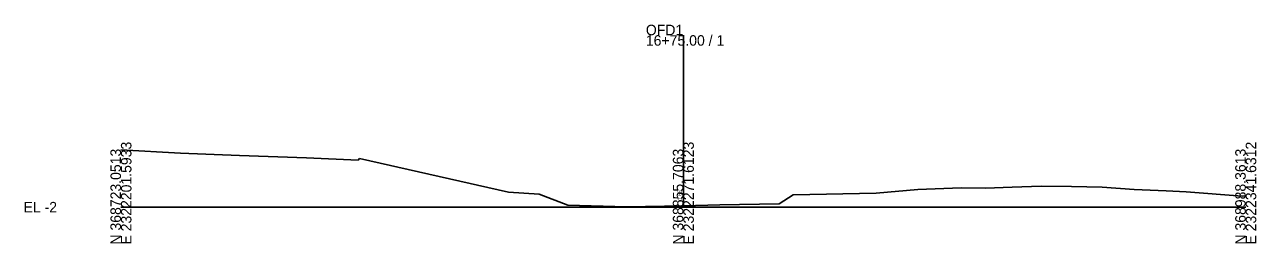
# Model space of a CAD drawing. Extents: x -26 to 303, y -10 to 14048.
# Drawn here: x -25.7 to 302.8, y 13490.3 to 13548.8 of the extents above; entities that cross this region are included whole.
import ezdxf

# ---------------------------------------------------------------- set-up
doc = ezdxf.new("R2010")
doc.units = 0
for name, color, linetype in [('RD_GPK_XS_Cell', 7, 'Continuous'), ('RD_XS_ExGround', 7, 'Continuous'), ('RD_XS_TX_Elev_EX', 7, 'Continuous')]:
    doc.layers.add(name, color=color, linetype=linetype)

msp = doc.modelspace()

# ---------------------------------------------------------------- linework, layer by layer
at = {"layer": 'RD_GPK_XS_Cell'}
for p, q in [((150, 13500), (150, 13545.96)), ((0, 13500), (150, 13500)), ((150, 13500), (300, 13500))]:
    msp.add_line(p, q, dxfattribs=at)
at = {"layer": 'RD_XS_ExGround'}
for p, q in [((0, 13515.32), (15.85, 13514.39)), ((15.85, 13514.39), (31.61, 13513.81)), ((31.61, 13513.81), (49.53, 13513.17)), ((49.53, 13513.17), (63.29, 13512.58)), ((63.29, 13512.58), (63.63, 13512.98)), ((63.63, 13512.98), (103.4, 13503.97)), ((103.4, 13503.97), (111.51, 13503.5)), ((111.51, 13503.5), (119.16, 13500.54)), ((175.53, 13500.93), (179.31, 13503.31)), ((179.31, 13503.31), (201.45, 13503.72)), ((201.45, 13503.72), (212.58, 13504.73)), ((212.58, 13504.73), (224.06, 13505.13)), ((224.06, 13505.13), (230.63, 13505.11)), ((230.63, 13505.11), (237.69, 13505.31)), ((237.69, 13505.31), (245.43, 13505.64)), ((245.43, 13505.64), (253.53, 13505.55)), ((253.53, 13505.55), (261.68, 13505.38)), ((261.68, 13505.38), (270.29, 13504.71)), ((270.29, 13504.71), (278.76, 13504.34)), ((278.76, 13504.34), (284.09, 13504.07)), ((284.09, 13504.07), (299.01, 13502.96)), ((299.01, 13502.96), (300, 13503.02)), ((119.16, 13500.54), (134.88, 13500.13)), ((134.88, 13500.13), (150, 13500.35)), ((150, 13500.35), (159.71, 13500.61)), ((159.71, 13500.61), (175.53, 13500.93))]:
    msp.add_line(p, q, dxfattribs=at)

# ---------------------------------------------------------------- texts
at = {"layer": 'RD_GPK_XS_Cell'}
for s, p in [('OFD1', (140, 13545.96)), ('16+75.00 / 1', (140, 13543.16)), ('EL -2', (-26, 13498.6))]:
    msp.add_text(s, height=2.8, dxfattribs=at).set_placement(p)
for s, p in [('E 2322201.5933', (2.8, 13490)), ('E 2322271.6123', (152.8, 13490)), ('E 2322341.6312', (302.8, 13490)), ('N 368723.0513', (0, 13490)), ('N 368855.7063', (150, 13490)), ('N 368988.3613', (300, 13490))]:
    msp.add_text(s, height=2.8, rotation=90, dxfattribs=at).set_placement(p)
at = {"layer": 'RD_XS_TX_Elev_EX'}
msp.add_text('-1.65', height=1, rotation=90, dxfattribs=at).set_placement((149.5, 13501.35))

doc.saveas('drawing.dxf')
